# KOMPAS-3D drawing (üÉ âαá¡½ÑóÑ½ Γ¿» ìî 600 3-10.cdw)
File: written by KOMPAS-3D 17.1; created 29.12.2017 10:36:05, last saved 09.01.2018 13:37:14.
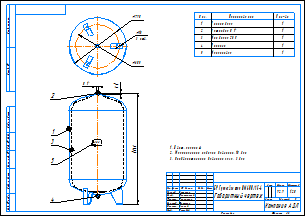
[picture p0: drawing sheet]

Sheet 1: A3, landscape, title-block layout from C:\Лощинин\GRAPHIC.LYT style 1

Title block, sheet 1: name: БР Гранлевел тип НМ 600/1,5-6 / Габаритный чертеж; mass: 92,9; sheets: 1; sheet format: A3; stored path: \\Fsk1\files\АП\20_PKO\02_Насосное направление\Разработка\04_Проекты разные\Баки\КД действующая\Баки Flexcon R\Компас\Чертежи\БР Гранлевел тип НМ 600 1,5-6.cdw; drawn by: Лощинин; checked by: Хантимеров

Views: Проекционный вид 2
Referenced files in \\Fsk1\files\АП\20_PKO\02_Насосное направление\Разработка\04_Проекты разные\Баки\КД действующая\Баки Flexcon R\Компас\: 600 литров.a3d, 16602_Flexcon_600_1-6.m3d
Referenced files in C:\Лощинин\: GRAPHIC.LYT
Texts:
  IvAn
  ADL
  Поз.
  Кол-во
  Корпус бака
  Мембрана SBR
  Патрубок G 1"
  Ниппель
  Маркировка
  АДЛ
  Цвет: красный
  Максимальное рабочее давление: 10 бар
  Предварительное давление газа: 3 бар
  ACAD_ISO03W100_RGB_223_127_255_SC_0.063_THICK_0.05
  ACAD_ISO03W100_RGB_223_127_255_SC_1_THICK_0.05
  Лит-Масса-Масштаб
  Материал-Предприятие
  Масштаб
  Изм.
  Лист
  № докум.
  Подп.
  Дата
  Лит.
  Разраб.
  Пров.
  Т.контр.
  Курлыкина
  Листов
  Нач.отд.
  Щетинин
  Н.контр.
  Долгов
  Утв.
  Рашидов
  Компания АДЛ
  Изменение
  Номер документа
  Подпись
  Обозначение документа
  Наименование изделия
  Масса изделия по ГОСТ 2.109-73
  Порядковый номер листа
  Общее количество листов в документе
  Характер работы, выполненной лицом, подписавшим документ
  Наименование или индекс предприятия, выпускающего документ
  Инв. № подл.
  Подп. и дата
  Взам. инв. №
  Инв. № дубл.
  Инвентарный номер подлинника по ГОСТ 2.501-68
  Подпись принявшего подлинник в отдел технической документации
  Инвентарный номер подлинника, взамен которого выпущен данный подлинник
  Инвентарный номер дубликата по ГОСТ 2.502-68
  Подпись принявшего дубликат в отдел технической документации
  Справ. №
  Перв. примен.
  Обозначение документа, взамен или на основании которого выпущен данный документ
  Обозначение документа, в котором впервые записан данный документ
  Подпись лица, копировавшего чертеж
  Обозначение формата листа
Dimensions and other numbers on the sheet: 1; 3; 2; 4; 5; 1540; 21; 1:20; 92,9; 16602_Flexcon_600_1-6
